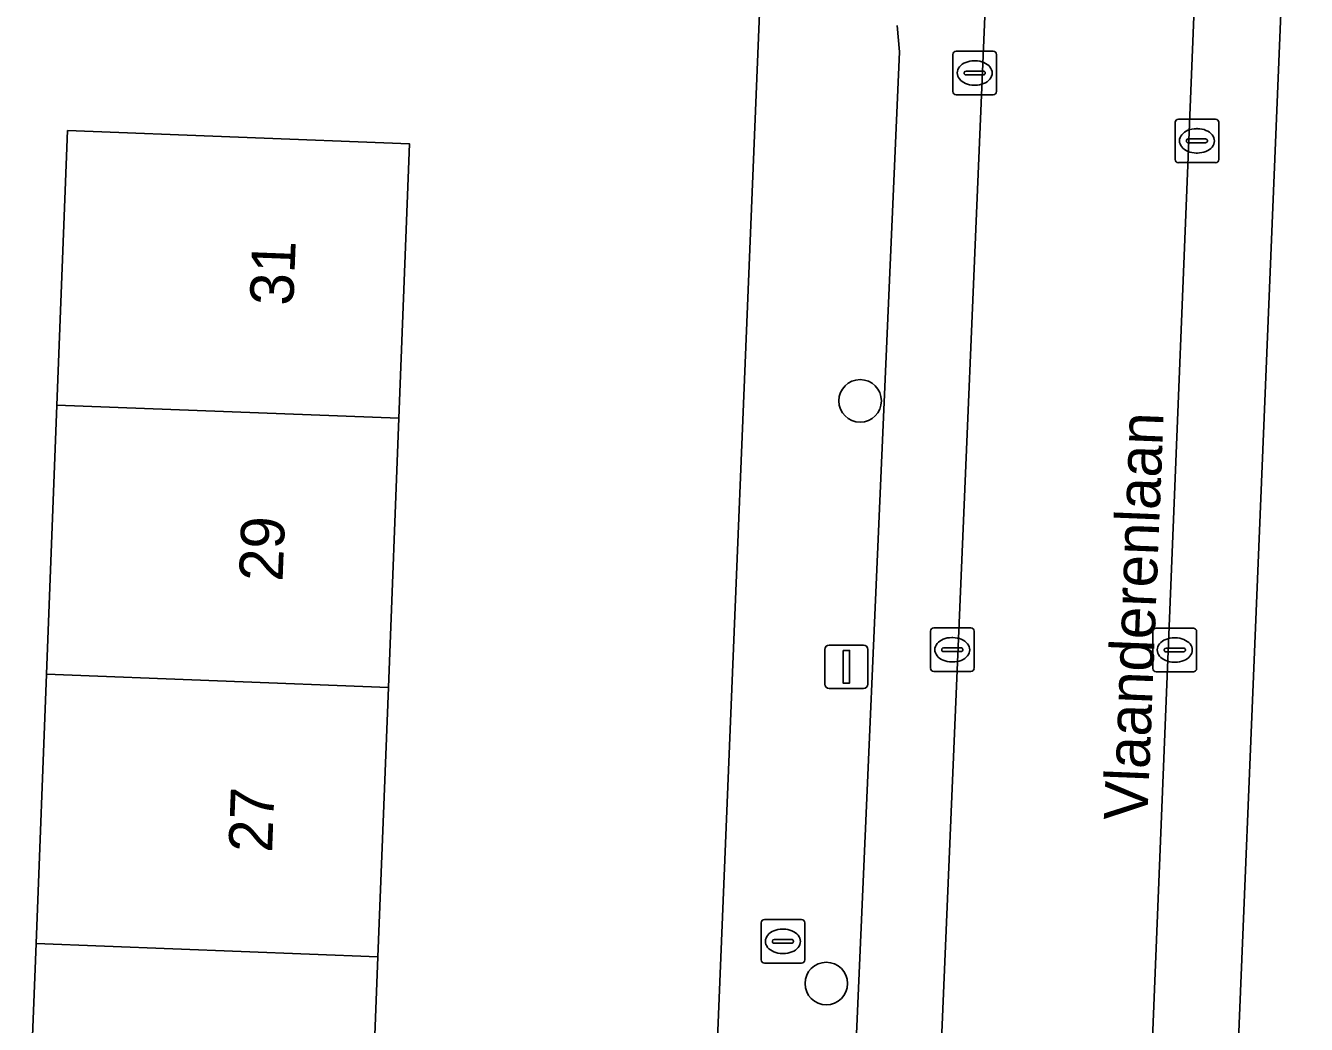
# Model space of a CAD drawing. Extents: x 160732 to 162107, y 387428 to 388479.
# Drawn here: x 161240.48 to 161269.86, y 387639.21 to 387662.13 of the extents above; entities that cross this region are included whole.
import ezdxf

# ---------------------------------------------------------------- set-up
doc = ezdxf.new("R2010")
doc.units = 0
for name, color, linetype in [('IMGEO_Boom', 7, 'Continuous'), ('IMGEO_Brandkraan', 7, 'Continuous'), ('IMGEO_Erf', 7, 'Continuous'), ('IMGEO_Kolk', 7, 'Continuous'), ('IMGEO_Lichtmast', 7, 'Continuous'), ('IMGEO_Openbare_ruimte_label', 7, 'Continuous'), ('IMGEO_Pand', 7, 'Continuous'), ('IMGEO_Pand_nummerreeks', 7, 'Continuous'), ('IMGEO_Parkeervlak_open', 7, 'Continuous'), ('IMGEO_Rijbaan_lokaal_open', 7, 'Continuous'), ('IMGEO_Voetpad_open', 7, 'Continuous')]:
    doc.layers.add(name, color=color, linetype=linetype)

msp = doc.modelspace()

# ---------------------------------------------------------------- linework, layer by layer
at = {"layer": 'IMGEO_Boom'}
for centre in [(161259.622, 387653.519), (161258.847, 387640.148)]:
    msp.add_circle(centre, 0.489, dxfattribs=at)
at = {"layer": 'IMGEO_Brandkraan'}
for p, q in [((161257.425, 387641.617), (161258.277, 387641.617)), ((161257.35, 387640.691), (161257.35, 387641.543)), ((161257.838, 387641.397), (161257.863, 387641.397)), ((161258.351, 387641.543), (161258.351, 387640.691)), ((161257.609, 387641.111), (161257.609, 387641.123)), ((161258.047, 387641.074), (161257.649, 387641.074)), ((161257.652, 387641.16), (161258.05, 387641.16)), ((161258.093, 387641.123), (161258.093, 387641.111)), ((161257.861, 387640.837), (161257.836, 387640.837)), ((161258.277, 387640.617), (161257.425, 387640.617))]:
    msp.add_line(p, q, dxfattribs=at)
for points in [[(161257.425, 387641.617), (161258.277, 387641.617)], [(161257.35, 387640.691), (161257.35, 387641.543)], [(161258.351, 387641.543), (161258.351, 387640.691)], [(161258.277, 387640.617), (161257.425, 387640.617)]]:
    msp.add_lwpolyline(points, dxfattribs=at)
for centre, radius, start, end in [((161257.427, 387641.541), 0.0765, 91.552, 178.448), ((161257.427, 387641.541), 0.0765, 91.552, 178.448), ((161258.275, 387641.541), 0.0765, 1.552, 88.448), ((161258.275, 387641.541), 0.0765, 1.552, 88.448), ((161257.649, 387641.12), 0.0403, 85.8775, 175.7526), ((161257.646, 387641.11), 0.0366, 178.938, 274.7102), ((161258.05, 387641.117), 0.043, 264.8664, 352.4533), ((161258.054, 387641.122), 0.0386, 1.7309, 96.639), ((161257.427, 387640.693), 0.0765, 181.552, 268.448), ((161257.427, 387640.693), 0.0765, 181.552, 268.448), ((161258.275, 387640.693), 0.0765, 271.552, 358.448), ((161258.275, 387640.693), 0.0765, 271.552, 358.448)]:
    msp.add_arc(centre, radius, start, end, dxfattribs=at)
for centre, major_axis, ratio, start_param, end_param in [((161257.837, 387641.117), (-0.387, 0.002), 0.722429, 4.712389, 7.853982), ((161257.862, 387641.117), (-0.39, 0.002), 0.717154, 1.570796, 4.712389)]:
    msp.add_ellipse(centre, major_axis=major_axis, ratio=ratio, start_param=start_param, end_param=end_param, dxfattribs=at)
at = {"layer": 'IMGEO_Erf'}
for points in [[(161255.697, 387622.916), (161255.813, 387623.394), (161256.242, 387633.829), (161256.468, 387633.87), (161256.778, 387638.497), (161256.334, 387638.507), (161257.384, 387664.107)], [(161240.475, 387634.888), (161240.714, 387641.067), (161240.954, 387647.246), (161241.193, 387653.425), (161241.437, 387659.723), (161249.282, 387659.419), (161249.038, 387653.121), (161248.798, 387646.942), (161248.559, 387640.763), (161248.319, 387634.584), (161248.079, 387628.404), (161247.834, 387622.086), (161254.025, 387621.801)]]:
    msp.add_lwpolyline(points, dxfattribs=at)
at = {"layer": 'IMGEO_Kolk'}
for p, q in [((161261.751, 387660.619), (161261.751, 387661.471)), ((161261.826, 387661.545), (161262.678, 387661.545)), ((161262.239, 387661.325), (161262.264, 387661.325)), ((161262.752, 387661.471), (161262.752, 387660.619)), ((161262.01, 387661.039), (161262.01, 387661.051)), ((161262.448, 387661.002), (161262.05, 387661.002)), ((161262.053, 387661.088), (161262.451, 387661.088)), ((161262.494, 387661.051), (161262.494, 387661.039)), ((161262.262, 387660.765), (161262.237, 387660.765)), ((161262.678, 387660.545), (161261.826, 387660.545)), ((161266.85, 387659.061), (161266.85, 387659.913)), ((161266.925, 387659.987), (161267.777, 387659.987)), ((161267.851, 387659.913), (161267.851, 387659.061)), ((161267.109, 387659.481), (161267.109, 387659.493)), ((161267.152, 387659.53), (161267.55, 387659.53)), ((161267.338, 387659.767), (161267.363, 387659.767)), ((161267.593, 387659.493), (161267.593, 387659.481)), ((161267.547, 387659.444), (161267.149, 387659.444)), ((161267.361, 387659.207), (161267.336, 387659.207)), ((161267.777, 387658.987), (161266.925, 387658.987)), ((161261.236, 387647.382), (161261.236, 387648.234)), ((161261.311, 387648.308), (161262.163, 387648.308)), ((161261.724, 387648.088), (161261.749, 387648.088)), ((161262.237, 387648.234), (161262.237, 387647.382)), ((161266.342, 387647.377), (161266.342, 387648.229)), ((161266.417, 387648.303), (161267.269, 387648.303)), ((161266.83, 387648.083), (161266.855, 387648.083)), ((161267.343, 387648.229), (161267.343, 387647.377)), ((161261.495, 387647.802), (161261.495, 387647.814)), ((161261.933, 387647.765), (161261.535, 387647.765)), ((161261.538, 387647.851), (161261.936, 387647.851)), ((161261.979, 387647.814), (161261.979, 387647.802)), ((161266.601, 387647.797), (161266.601, 387647.809)), ((161267.039, 387647.76), (161266.641, 387647.76)), ((161266.644, 387647.846), (161267.042, 387647.846)), ((161267.085, 387647.809), (161267.085, 387647.797)), ((161261.747, 387647.528), (161261.722, 387647.528)), ((161266.853, 387647.523), (161266.828, 387647.523)), ((161262.163, 387647.308), (161261.311, 387647.308)), ((161267.269, 387647.303), (161266.417, 387647.303))]:
    msp.add_line(p, q, dxfattribs=at)
for points in [[(161261.751, 387660.619), (161261.751, 387661.471)], [(161261.826, 387661.545), (161262.678, 387661.545)], [(161262.752, 387661.471), (161262.752, 387660.619)], [(161262.678, 387660.545), (161261.826, 387660.545)], [(161266.85, 387659.061), (161266.85, 387659.913)], [(161266.925, 387659.987), (161267.777, 387659.987)], [(161267.851, 387659.913), (161267.851, 387659.061)], [(161267.777, 387658.987), (161266.925, 387658.987)], [(161261.236, 387647.382), (161261.236, 387648.234)], [(161261.311, 387648.308), (161262.163, 387648.308)], [(161262.237, 387648.234), (161262.237, 387647.382)], [(161266.342, 387647.377), (161266.342, 387648.229)], [(161266.417, 387648.303), (161267.269, 387648.303)], [(161267.343, 387648.229), (161267.343, 387647.377)], [(161262.163, 387647.308), (161261.311, 387647.308)], [(161267.269, 387647.303), (161266.417, 387647.303)]]:
    msp.add_lwpolyline(points, dxfattribs=at)
for centre, radius, start, end in [((161261.828, 387661.469), 0.0765, 91.552, 178.448), ((161261.828, 387661.469), 0.0765, 91.552, 178.448), ((161262.676, 387661.469), 0.0765, 1.552, 88.448), ((161262.676, 387661.469), 0.0765, 1.552, 88.448), ((161262.05, 387661.048), 0.0403, 85.8775, 175.7526), ((161262.047, 387661.038), 0.0366, 178.938, 274.7102), ((161262.451, 387661.045), 0.043, 264.8664, 352.4533), ((161262.455, 387661.05), 0.0386, 1.7309, 96.639), ((161261.828, 387660.621), 0.0765, 181.552, 268.448), ((161261.828, 387660.621), 0.0765, 181.552, 268.448), ((161262.676, 387660.621), 0.0765, 271.552, 358.448), ((161262.676, 387660.621), 0.0765, 271.552, 358.448), ((161266.927, 387659.911), 0.0765, 91.552, 178.448), ((161266.927, 387659.911), 0.0765, 91.552, 178.448), ((161267.775, 387659.911), 0.0765, 1.552, 88.448), ((161267.775, 387659.911), 0.0765, 1.552, 88.448), ((161267.149, 387659.49), 0.0403, 85.8775, 175.7526), ((161267.554, 387659.492), 0.0386, 1.7309, 96.639), ((161267.146, 387659.48), 0.0366, 178.938, 274.7102), ((161267.55, 387659.487), 0.043, 264.8664, 352.4533), ((161266.927, 387659.063), 0.0765, 181.552, 268.448), ((161266.927, 387659.063), 0.0765, 181.552, 268.448), ((161267.775, 387659.063), 0.0765, 271.552, 358.448), ((161267.775, 387659.063), 0.0765, 271.552, 358.448), ((161261.313, 387648.232), 0.0765, 91.552, 178.448), ((161261.313, 387648.232), 0.0765, 91.552, 178.448), ((161262.161, 387648.232), 0.0765, 1.552, 88.448), ((161262.161, 387648.232), 0.0765, 1.552, 88.448), ((161266.419, 387648.227), 0.0765, 91.552, 178.448), ((161266.419, 387648.227), 0.0765, 91.552, 178.448), ((161267.267, 387648.227), 0.0765, 1.552, 88.448), ((161267.267, 387648.227), 0.0765, 1.552, 88.448), ((161261.535, 387647.811), 0.0403, 85.8775, 175.7526), ((161261.532, 387647.801), 0.0366, 178.938, 274.7102), ((161261.936, 387647.808), 0.043, 264.8664, 352.4533), ((161261.94, 387647.813), 0.0386, 1.7309, 96.639), ((161266.641, 387647.806), 0.0403, 85.8775, 175.7526), ((161266.638, 387647.796), 0.0366, 178.938, 274.7102), ((161267.042, 387647.803), 0.043, 264.8664, 352.4533), ((161267.046, 387647.808), 0.0386, 1.7309, 96.639), ((161261.313, 387647.384), 0.0765, 181.552, 268.448), ((161261.313, 387647.384), 0.0765, 181.552, 268.448), ((161262.161, 387647.384), 0.0765, 271.552, 358.448), ((161262.161, 387647.384), 0.0765, 271.552, 358.448), ((161266.419, 387647.379), 0.0765, 181.552, 268.448), ((161266.419, 387647.379), 0.0765, 181.552, 268.448), ((161267.267, 387647.379), 0.0765, 271.552, 358.448), ((161267.267, 387647.379), 0.0765, 271.552, 358.448)]:
    msp.add_arc(centre, radius, start, end, dxfattribs=at)
for centre, major_axis, ratio, start_param, end_param in [((161262.238, 387661.045), (-0.387, 0.002), 0.722429, 4.712389, 7.853982), ((161262.263, 387661.045), (-0.39, 0.002), 0.717154, 1.570796, 4.712389), ((161267.337, 387659.487), (-0.387, 0.002), 0.722429, 4.712389, 7.853982), ((161267.362, 387659.487), (-0.39, 0.002), 0.717154, 1.570796, 4.712389), ((161261.723, 387647.808), (-0.387, 0.002), 0.722429, 4.712389, 7.853982), ((161261.748, 387647.808), (-0.39, 0.002), 0.717154, 1.570796, 4.712389), ((161266.829, 387647.803), (-0.387, 0.002), 0.722429, 4.712389, 7.853982), ((161266.854, 387647.803), (-0.39, 0.002), 0.717154, 1.570796, 4.712389)]:
    msp.add_ellipse(centre, major_axis=major_axis, ratio=ratio, start_param=start_param, end_param=end_param, dxfattribs=at)
at = {"layer": 'IMGEO_Lichtmast'}
for p, q in [((161258.812, 387647.017), (161258.812, 387647.817)), ((161258.812, 387647.817), (161258.812, 387647.017)), ((161258.912, 387647.917), (161259.702, 387647.917)), ((161259.702, 387647.917), (161258.912, 387647.917)), ((161259.802, 387647.817), (161259.802, 387647.017)), ((161259.802, 387647.017), (161259.802, 387647.817)), ((161259.702, 387646.917), (161258.912, 387646.917)), ((161258.912, 387646.917), (161259.702, 387646.917))]:
    msp.add_line(p, q, dxfattribs=at)
msp.add_lwpolyline([(161259.232, 387647.792), (161259.382, 387647.792), (161259.382, 387647.042), (161259.232, 387647.042), (161259.232, 387647.792)], dxfattribs=at)
for centre, start, end in [((161258.912, 387647.817), 90, 180), ((161258.912, 387647.817), 90, 180), ((161259.702, 387647.817), 0, 90), ((161259.702, 387647.817), 360, 90), ((161258.912, 387647.017), 180, 270), ((161258.912, 387647.017), 180, 270), ((161259.702, 387647.017), 270, 0), ((161259.702, 387647.017), 270, 0)]:
    msp.add_arc(centre, 0.1, start, end, dxfattribs=at)
at = {"layer": 'IMGEO_Pand'}
for points in [[(161249.038, 387653.121), (161249.282, 387659.419), (161241.437, 387659.723), (161241.193, 387653.425)], [(161248.798, 387646.942), (161249.038, 387653.121), (161241.193, 387653.425), (161240.954, 387647.246)], [(161240.954, 387647.246), (161240.714, 387641.067), (161248.559, 387640.763), (161248.798, 387646.942)], [(161248.319, 387634.584), (161248.559, 387640.763), (161240.714, 387641.067), (161240.475, 387634.888)]]:
    msp.add_lwpolyline(points, close=True, dxfattribs=at)
at = {"layer": 'IMGEO_Parkeervlak_open'}
for points in [[(161267.994, 387679.937), (161265.947, 387629.426)], [(161268.048, 387632.547), (161269.862, 387676.707)], [(161261.068, 387628.897), (161262.491, 387662.523), (161262.61, 387665.342)], [(161260.471, 387662.132), (161260.529, 387661.534), (161259.234, 387632.002)]]:
    msp.add_lwpolyline(points, dxfattribs=at)
at = {"layer": 'IMGEO_Rijbaan_lokaal_open'}
msp.add_lwpolyline([(161261.068, 387628.897), (161261.039, 387627.352), (161265.876, 387627.177), (161265.947, 387629.426), (161267.994, 387679.937), (161268.004, 387680.2), (161263.268, 387680.453), (161262.765, 387669.23), (161262.61, 387665.342), (161262.491, 387662.523)], close=True, dxfattribs=at)
at = {"layer": 'IMGEO_Voetpad_open'}
for points in [[(161269.862, 387676.707), (161268.048, 387632.547)], [(161257.384, 387664.107), (161256.334, 387638.507), (161256.778, 387638.497), (161256.468, 387633.87), (161256.242, 387633.829), (161255.813, 387623.394), (161255.697, 387622.916)], [(161259.234, 387632.002), (161260.529, 387661.534), (161260.471, 387662.132)]]:
    msp.add_lwpolyline(points, dxfattribs=at)

# ---------------------------------------------------------------- texts
at = {"layer": 'IMGEO_Openbare_ruimte_label'}
msp.add_text('Vlaanderenlaan', height=1, rotation=87.7071, dxfattribs=at).set_placement((161266.212, 387643.875))
at = {"layer": 'IMGEO_Pand_nummerreeks'}
for s, p in [('31', (161246.616, 387655.695)), ('29', (161246.37, 387649.363)), ('27', (161246.129, 387643.143))]:
    msp.add_text(s, height=1, rotation=87.7793, dxfattribs=at).set_placement(p)

doc.saveas('drawing.dxf')
